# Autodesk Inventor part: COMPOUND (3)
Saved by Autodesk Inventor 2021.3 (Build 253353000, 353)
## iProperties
Created: 2022-06
Part Number: COMPOUND (3)
Material: Generic
Document SubType Name: Modeling
Designer: Administrator
Density: 1 g/cm^3
Appearance: Default
Title: COMPOUND (3)
Author: Administrator
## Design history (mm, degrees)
feature "Body1"
feature "Body2"
feature "Body3"
feature "Body4"
feature "Body5"
feature "Body6"
feature "Body7"
feature "Body8"
feature "Body9"
feature "Body10"
feature "Body11"
feature "Body12"
feature "Body13"
feature "Body14"
feature "Body15"
feature "Body16"
feature "Body17"
feature "Body18"
body "Solid1"
body "Solid2"
body "Solid3"
body "Solid4"
body "Solid5"
body "Solid6"
body "Solid7"
body "Solid8"
body "Solid9"
body "Solid10"
body "Solid11"
body "Solid12"
body "Solid13"
body "Solid14"
body "Solid15"
body "Solid16"
body "Solid17"
body "Solid18"
